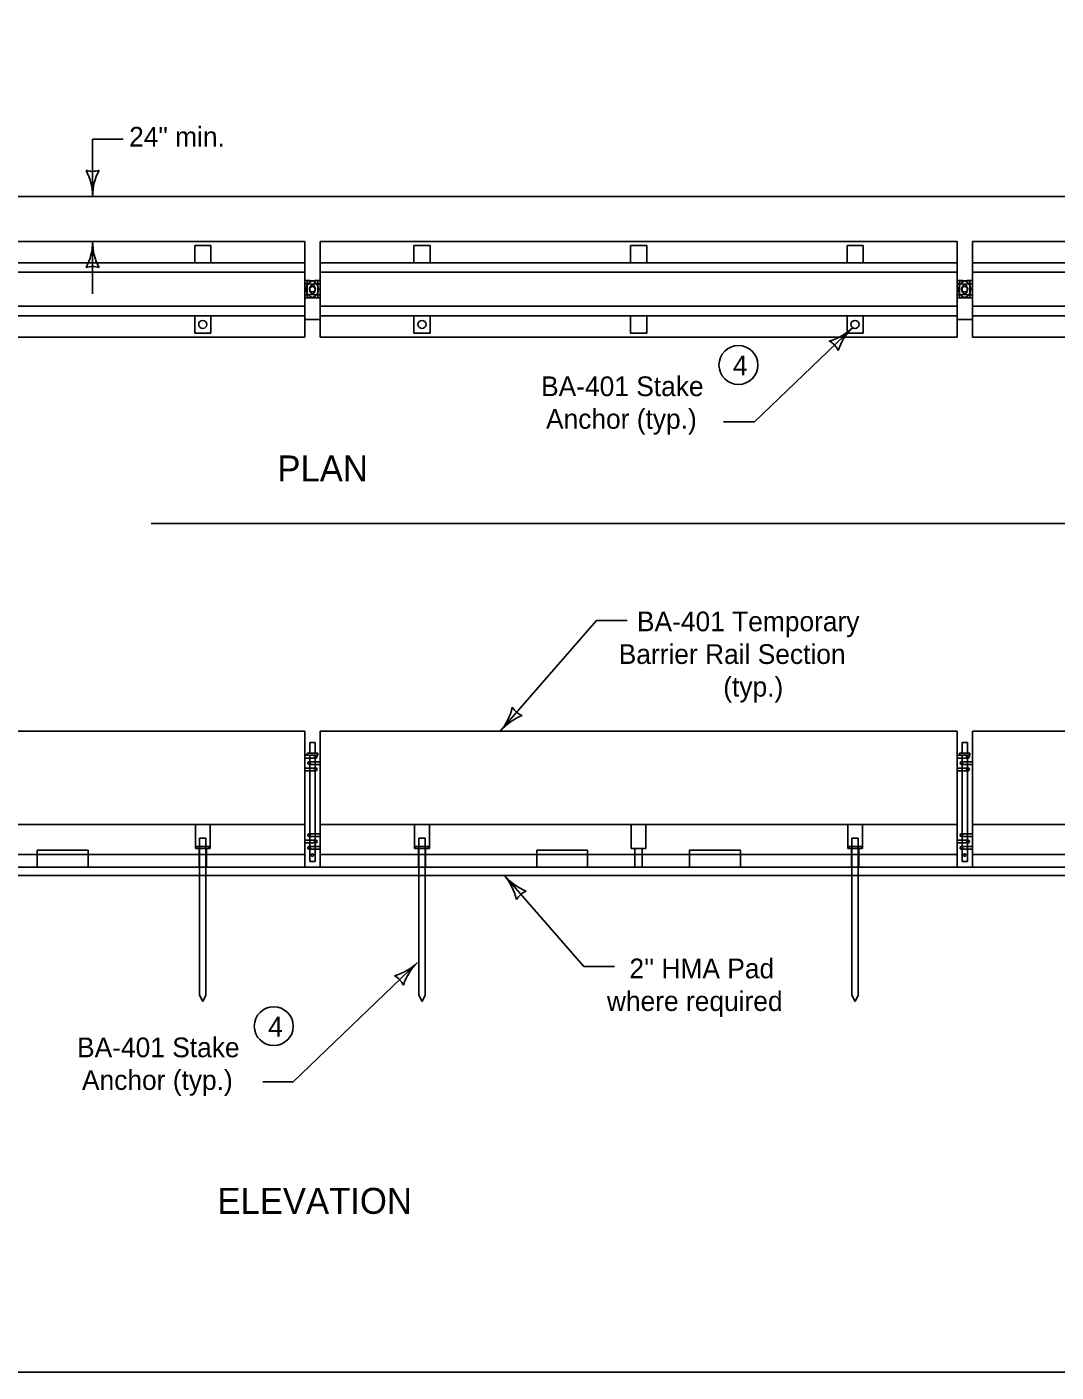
# Model space of a CAD drawing. Extents: x 10028 to 81668, y 3581 to 11018.
# Drawn here: x 18550 to 19344, y 7924 to 8962 of the extents above; entities that cross this region are included whole.
import ezdxf

# ---------------------------------------------------------------- set-up
doc = ezdxf.new("R2010")
doc.units = 0
for name, color, linetype in [('conPaving', 7, 'Continuous'), ('dsnCellsNorthArrow', 7, 'Continuous'), ('dsnTextTabulation', 7, 'Continuous'), ('Level 41', 7, 'Continuous'), ('Level 9', 7, 'Continuous'), ('SheetBorder', 7, 'Continuous')]:
    doc.layers.add(name, color=color, linetype=linetype)

msp = doc.modelspace()

# ---------------------------------------------------------------- linework, layer by layer
at = {"layer": 'conPaving'}
for p, q in [((18683.3, 8313.6), (18682.9, 8313.6)), ((18683.3, 8307.1), (18683.3, 8313.6)), ((18688.6, 8313.6), (18688.2, 8313.6)), ((18688.2, 8313.6), (18688.2, 8307.1)), ((18764.1, 8313.6), (18688.6, 8313.6)), ((18852.5, 8313.6), (18852.1, 8313.6)), ((18852.5, 8307.1), (18852.5, 8313.6)), ((18857.4, 8313.6), (18857.4, 8307.1)), ((19100.7, 8313.6), (19061.3, 8313.6)), ((19186.7, 8307.1), (19186.7, 8313.6)), ((19191.6, 8313.6), (19191.6, 8307.1)), ((18521.1, 8307.1), (18683.3, 8307.1)), ((18688.2, 8307.1), (18852.5, 8307.1)), ((18857.4, 8307.1), (18918.6, 8307.1)), ((18918.6, 8307.1), (19186.7, 8307.1)), ((19191.6, 8307.1), (19355.9, 8307.1))]:
    msp.add_line(p, q, dxfattribs=at)
for points in [[(18682.9, 8313.6), (18597.3, 8313.6), (18557.9, 8313.6), (18521.5, 8313.6), (18521.1, 8313.6)], [(18852.1, 8313.6), (18776.5, 8313.6), (18764.1, 8313.6)], [(19019.2, 8313.6), (18982.7, 8313.6), (18943.4, 8313.6), (18857.7, 8313.6), (18857.4, 8313.6)], [(19061.3, 8313.6), (19024.9, 8313.6), (19019.2, 8313.6)], [(19186.7, 8313.6), (19186.3, 8313.6), (19100.7, 8313.6)], [(19279.9, 8313.6), (19267.5, 8313.6), (19192, 8313.6), (19191.6, 8313.6)], [(19355.9, 8313.6), (19355.5, 8313.6), (19279.9, 8313.6)], [(18918.6, 8307.1), (18918.6, 8307.1)]]:
    msp.add_lwpolyline(points, dxfattribs=at)
msp.add_arc((18950.9, 8334.6), 42.5, 220.4336, 220.435, dxfattribs=at)
at = {"layer": 'dsnTextTabulation'}
for p, q in [((18600.7, 8831), (18600.7, 8875.1)), ((18600.7, 8875.1), (18624.3, 8875.1)), ((18764.4, 8796.1), (18272.9, 8796.1)), ((18600.7, 8755.8), (18600.7, 8796.1)), ((18764.4, 8722.4), (18764.4, 8796.1)), ((19267.8, 8796.1), (18776.3, 8796.1)), ((18776.3, 8722.4), (18776.3, 8796.1)), ((19267.8, 8722.4), (19267.8, 8796.1)), ((19771.2, 8796.1), (19279.7, 8796.1)), ((19279.7, 8722.4), (19279.7, 8796.1)), ((18764.4, 8779.8), (18272.9, 8779.8)), ((19267.8, 8779.8), (18776.3, 8779.8)), ((19771.2, 8779.8), (19279.7, 8779.8)), ((18764.4, 8772.4), (18272.9, 8772.4)), ((19267.8, 8772.4), (18776.3, 8772.4)), ((19771.2, 8772.4), (19279.7, 8772.4)), ((18764.4, 8746.2), (18272.9, 8746.2)), ((18764.4, 8738.8), (18272.9, 8738.8)), ((19267.8, 8746.2), (18776.3, 8746.2)), ((19267.8, 8738.8), (18776.3, 8738.8)), ((19771.2, 8746.2), (19279.7, 8746.2)), ((19771.2, 8738.8), (19279.7, 8738.8)), ((19111.4, 8657), (19187.1, 8729.7)), ((18764.4, 8722.4), (18272.9, 8722.4)), ((19267.8, 8722.4), (18776.3, 8722.4)), ((19771.2, 8722.4), (19279.7, 8722.4)), ((19087.7, 8657), (19111.4, 8657)), ((18645.9, 8578.7), (19777.1, 8578.7)), ((18915.3, 8418.5), (18989.6, 8503.7)), ((18989.6, 8503.7), (19013.2, 8503.7)), ((18272.9, 8418.5), (18764.4, 8418.5)), ((18764.4, 8313.9), (18764.4, 8418.5)), ((18776.3, 8313.9), (18776.3, 8418.5)), ((18776.3, 8418.5), (19267.8, 8418.5)), ((19267.8, 8313.9), (19267.8, 8418.5)), ((19279.7, 8313.9), (19279.7, 8418.5)), ((19279.7, 8418.5), (19771.2, 8418.5)), ((18272.9, 8346.4), (18764.4, 8346.4)), ((18776.3, 8346.4), (19267.8, 8346.4)), ((19279.7, 8346.4), (19771.2, 8346.4)), ((18272.9, 8323.4), (18764.4, 8323.4)), ((18557.9, 8326.7), (18597.3, 8326.7)), ((18557.9, 8313.6), (18557.9, 8323.4)), ((18597.3, 8313.6), (18597.3, 8323.4)), ((18776.3, 8323.4), (19267.8, 8323.4)), ((18943.4, 8326.7), (18982.7, 8326.7)), ((18943.4, 8313.6), (18943.4, 8323.4)), ((18982.7, 8313.6), (18982.7, 8323.4)), ((19061.3, 8326.7), (19100.7, 8326.7)), ((19061.3, 8313.6), (19061.3, 8323.4)), ((19100.7, 8313.6), (19100.7, 8323.4)), ((19279.7, 8323.4), (19771.2, 8323.4)), ((18479.3, 8313.6), (18557.9, 8313.6)), ((18597.3, 8313.6), (18764.1, 8313.6)), ((18776.5, 8313.6), (18943.4, 8313.6)), ((18982.7, 8313.6), (19061.3, 8313.6)), ((19100.7, 8313.6), (19267.5, 8313.6)), ((19279.9, 8313.6), (19446.8, 8313.6)), ((18918.6, 8307.1), (18979.8, 8236.8)), ((18755.6, 8148), (18851.5, 8239.9)), ((18979.8, 8236.8), (19003.4, 8236.8)), ((18732, 8148), (18755.6, 8148))]:
    msp.add_line(p, q, dxfattribs=at)
for centre in [(19099.1, 8700.9), (18740.5, 8190.9)]:
    msp.add_circle(centre, 15, dxfattribs=at)
for centre, radius, start, end in [((18600.7, 8866.7), 16.4, 252.2666, 287.7333), ((18558.2, 8831), 42.5, 360, 28.0725), ((18643.2, 8831), 42.5, 151.9275, 180), ((18558.2, 8796.1), 42.5, 331.9275, 360), ((18643.2, 8796.1), 42.5, 180, 208.0725), ((18600.7, 8760.5), 16.4, 72.2666, 107.7334), ((19157.7, 8760.3), 42.5, 285.7371, 313.8096), ((19216.5, 8699), 42.5, 133.8096, 161.8821), ((19161.4, 8705), 16.4, 26.0762, 61.5429), ((18883, 8446), 42.5, 319.5664, 347.6389), ((18938.5, 8445.6), 16.4, 211.833, 247.2997), ((18947.7, 8390.9), 42.5, 111.4939, 139.5664), ((18886.2, 8279.5), 42.5, 12.3611, 40.4336), ((18950.9, 8334.6), 42.5, 220.4336, 248.5061), ((18941.7, 8279.9), 16.4, 112.7003, 148.167), ((18822.1, 8270.6), 42.5, 285.7371, 313.8096), ((18880.9, 8209.3), 42.5, 133.8096, 161.8821), ((18825.8, 8215.3), 16.4, 26.0762, 61.5429)]:
    msp.add_arc(centre, radius, start, end, dxfattribs=at)
at = {"layer": 'Level 41'}
for p, q in [((18679.5, 8793), (18679.5, 8779.8)), ((18679.5, 8793), (18692, 8793)), ((18692, 8793), (18692, 8779.8)), ((18848.6, 8793), (18861.2, 8793)), ((18848.6, 8793), (18848.6, 8779.8)), ((18861.2, 8793), (18861.2, 8779.8)), ((19015.7, 8793), (19028.3, 8793)), ((19015.7, 8793), (19015.7, 8779.8)), ((19028.3, 8793), (19028.3, 8779.8)), ((19182.9, 8793), (19182.9, 8779.8)), ((19182.9, 8793), (19195.4, 8793)), ((19195.4, 8793), (19195.4, 8779.8)), ((18764.4, 8766), (18768.3, 8766)), ((18764.4, 8763.6), (18768.3, 8763.6)), ((18776.3, 8766), (18772.3, 8766)), ((18776.3, 8763.6), (18772.3, 8763.6)), ((19267.8, 8766), (19271.7, 8766)), ((19267.8, 8763.6), (19271.7, 8763.6)), ((19279.7, 8766), (19275.7, 8766)), ((19279.7, 8763.6), (19275.7, 8763.6)), ((18764.4, 8755), (18768.3, 8755)), ((18764.4, 8752.6), (18768.3, 8752.6)), ((18776.3, 8755), (18772.3, 8755)), ((18776.3, 8752.6), (18772.3, 8752.6)), ((19267.8, 8755), (19271.7, 8755)), ((19267.8, 8752.6), (19271.7, 8752.6)), ((19279.7, 8755), (19275.7, 8755)), ((19279.7, 8752.6), (19275.7, 8752.6)), ((18679.5, 8738.8), (18679.5, 8725.5)), ((18692, 8738.8), (18692, 8725.5)), ((18848.6, 8738.8), (18848.6, 8725.5)), ((18861.2, 8738.8), (18861.2, 8725.5)), ((19015.7, 8738.8), (19015.7, 8725.5)), ((19028.3, 8738.8), (19028.3, 8725.5)), ((19182.9, 8738.8), (19182.9, 8725.5)), ((19195.4, 8738.8), (19195.4, 8725.5)), ((18679.5, 8725.5), (18692, 8725.5)), ((18848.6, 8725.5), (18861.2, 8725.5)), ((19015.7, 8725.5), (19028.3, 8725.5)), ((19182.9, 8725.5), (19195.4, 8725.5)), ((18764.4, 8399.9), (18772.9, 8399.9)), ((18764.4, 8397.7), (18772.9, 8397.7)), ((19267.8, 8399.9), (19276.3, 8399.9)), ((19267.8, 8397.7), (19276.3, 8397.7)), ((18764.4, 8390), (18772.9, 8390)), ((18764.4, 8387.9), (18772.9, 8387.9)), ((18767.8, 8394.9), (18776.3, 8394.9)), ((18767.8, 8392.8), (18776.3, 8392.8)), ((19267.8, 8390), (19276.3, 8390)), ((19267.8, 8387.9), (19276.3, 8387.9)), ((19271.2, 8394.9), (19279.7, 8394.9)), ((19271.2, 8392.8), (19279.7, 8392.8)), ((18680.1, 8327.8), (18680.1, 8346.4)), ((18691.4, 8327.8), (18691.4, 8346.4)), ((18849.2, 8327.8), (18849.2, 8346.4)), ((18860.6, 8327.8), (18860.6, 8346.4)), ((19016.4, 8327.8), (19016.4, 8346.4)), ((19027.7, 8327.8), (19027.7, 8346.4)), ((19183.5, 8327.8), (19183.5, 8346.4)), ((19194.8, 8327.8), (19194.8, 8346.4)), ((18764.4, 8334.3), (18772.9, 8334.3)), ((18767.8, 8339.2), (18776.3, 8339.2)), ((18767.8, 8337.1), (18776.3, 8337.1)), ((19267.8, 8334.3), (19276.3, 8334.3)), ((19271.2, 8339.2), (19279.7, 8339.2)), ((19271.2, 8337.1), (19279.7, 8337.1)), ((18680.1, 8327.8), (18691.4, 8327.8)), ((18682.9, 8313.6), (18682.9, 8327.8)), ((18688.6, 8313.6), (18688.6, 8327.8)), ((18764.4, 8332.2), (18772.9, 8332.2)), ((18767.8, 8329.4), (18776.3, 8329.4)), ((18767.8, 8327.3), (18776.3, 8327.3)), ((18849.2, 8327.8), (18860.6, 8327.8)), ((18852.1, 8313.6), (18852.1, 8327.8)), ((18857.7, 8313.6), (18857.7, 8327.8)), ((19016.4, 8327.8), (19027.7, 8327.8)), ((19019.2, 8313.6), (19019.2, 8327.8)), ((19024.9, 8313.6), (19024.9, 8327.8)), ((19183.5, 8327.8), (19194.8, 8327.8)), ((19186.3, 8313.6), (19186.3, 8327.8)), ((19192, 8313.6), (19192, 8327.8)), ((19267.8, 8332.2), (19276.3, 8332.2)), ((19271.2, 8329.4), (19279.7, 8329.4)), ((19271.2, 8327.3), (19279.7, 8327.3))]:
    msp.add_line(p, q, dxfattribs=at)
for centre, radius in [((18685.7, 8732.2), 3.15), ((18854.9, 8732.2), 3.15), ((19189.1, 8732.2), 3.15), ((18772.9, 8398.8), 1.06), ((19276.3, 8398.8), 1.06), ((18767.8, 8393.9), 1.06), ((18772.9, 8389), 1.06), ((19271.2, 8393.9), 1.06), ((19276.3, 8389), 1.06), ((18767.8, 8338.2), 1.06), ((18772.9, 8333.3), 1.06), ((19271.2, 8338.2), 1.06), ((19276.3, 8333.3), 1.06), ((18767.8, 8328.4), 1.06), ((19271.2, 8328.4), 1.06)]:
    msp.add_circle(centre, radius, dxfattribs=at)
for centre, radius, start, end in [((18772.3, 8759.3), 6.68, 90, 270), ((18772.3, 8759.3), 4.33, 90, 270), ((18768.3, 8759.3), 6.68, 270, 90), ((18768.3, 8759.3), 4.33, 270, 90), ((19275.7, 8759.3), 6.68, 90, 270), ((19275.7, 8759.3), 4.33, 90, 270), ((19271.7, 8759.3), 6.68, 270, 90), ((19271.7, 8759.3), 4.33, 270, 90)]:
    msp.add_arc(centre, radius, start, end, dxfattribs=at)
at = {"layer": 'Level 9'}
for p, q in [((17757.6, 8831), (19777.1, 8831)), ((18776.3, 8796.1), (19267.8, 8796.1)), ((19279.7, 8796.1), (19771.2, 8796.1)), ((18764.4, 8766), (18768.3, 8766)), ((18766.2, 8765.8), (18774.4, 8765.8)), ((18766.2, 8752.7), (18766.2, 8765.8)), ((18769.8, 8765.8), (18770.9, 8765.8)), ((18772.3, 8766), (18776.3, 8766)), ((18774.4, 8765.8), (18774.4, 8752.7)), ((19267.8, 8766), (19271.7, 8766)), ((19269.6, 8765.8), (19277.8, 8765.8)), ((19269.6, 8752.7), (19269.6, 8765.8)), ((19273.2, 8765.8), (19274.3, 8765.8)), ((19275.7, 8766), (19279.7, 8766)), ((19277.8, 8765.8), (19277.8, 8752.7)), ((18768.3, 8752.6), (18764.4, 8752.6)), ((18774.4, 8752.7), (18766.2, 8752.7)), ((18771.1, 8752.7), (18769.5, 8752.7)), ((18776.3, 8752.6), (18772.3, 8752.6)), ((19271.7, 8752.6), (19267.8, 8752.6)), ((19277.8, 8752.7), (19269.6, 8752.7)), ((19274.5, 8752.7), (19272.9, 8752.7)), ((19279.7, 8752.6), (19275.7, 8752.6)), ((18764.4, 8736), (18776.3, 8736)), ((18764.4, 8736), (18776.3, 8736)), ((19267.8, 8736), (19279.7, 8736)), ((19267.8, 8736), (19279.7, 8736)), ((18768.3, 8409.7), (18772.4, 8409.7)), ((18768.3, 8401.5), (18768.3, 8409.7)), ((18772.4, 8409.7), (18772.4, 8401.5)), ((19271.7, 8409.7), (19275.8, 8409.7)), ((19271.7, 8401.5), (19271.7, 8409.7)), ((19275.8, 8409.7), (19275.8, 8401.5)), ((18766.2, 8401.5), (18774.4, 8401.5)), ((18766.2, 8399.9), (18766.2, 8401.5)), ((18774.4, 8399.9), (18766.2, 8399.9)), ((18768.3, 8317.9), (18768.3, 8399.9)), ((18772.4, 8399.9), (18772.4, 8317.9)), ((18774.4, 8401.5), (18774.4, 8399.9)), ((19269.6, 8401.5), (19277.8, 8401.5)), ((19269.6, 8399.9), (19269.6, 8401.5)), ((19277.8, 8399.9), (19269.6, 8399.9)), ((19271.7, 8317.9), (19271.7, 8399.9)), ((19275.8, 8399.9), (19275.8, 8317.9)), ((19277.8, 8401.5), (19277.8, 8399.9)), ((18688.2, 8336), (18683.3, 8336)), ((18683.3, 8336), (18683.3, 8329.4)), ((18688.2, 8336), (18683.3, 8336)), ((18683.3, 8214.8), (18683.3, 8336)), ((18688.2, 8329.4), (18688.2, 8336)), ((18688.2, 8214.8), (18688.2, 8336)), ((18857.4, 8336), (18852.5, 8336)), ((18852.5, 8336), (18852.5, 8329.4)), ((18857.4, 8336), (18852.5, 8336)), ((18852.5, 8214.8), (18852.5, 8336)), ((18857.4, 8329.4), (18857.4, 8336)), ((18857.4, 8214.8), (18857.4, 8336)), ((19191.6, 8336), (19186.7, 8336)), ((19186.7, 8336), (19186.7, 8329.4)), ((19191.6, 8336), (19186.7, 8336)), ((19186.7, 8214.8), (19186.7, 8336)), ((19191.6, 8329.4), (19191.6, 8336)), ((19191.6, 8214.8), (19191.6, 8336)), ((18557.9, 8323.4), (18557.9, 8326.7)), ((18557.9, 8323.4), (18597.3, 8323.4)), ((18597.3, 8323.4), (18597.3, 8326.7)), ((18680.8, 8329.4), (18680.8, 8327.8)), ((18683.3, 8329.4), (18680.8, 8329.4)), ((18680.8, 8327.8), (18680.8, 8329.4)), ((18680.8, 8327.8), (18682.9, 8327.8)), ((18682.9, 8327.8), (18683.3, 8327.8)), ((18688.2, 8329.4), (18683.3, 8329.4)), ((18683.3, 8329.4), (18683.3, 8327.8)), ((18683.3, 8327.8), (18683.3, 8329.4)), ((18683.3, 8329.4), (18688.2, 8329.4)), ((18688.2, 8327.8), (18683.3, 8327.8)), ((18683.3, 8327.8), (18683.3, 8323.4)), ((18683.3, 8327.8), (18688.2, 8327.8)), ((18688.2, 8323.4), (18683.3, 8323.4)), ((18683.3, 8323.4), (18683.3, 8313.6)), ((18683.3, 8323.4), (18688.2, 8323.4)), ((18688.2, 8327.8), (18688.2, 8329.4)), ((18688.2, 8329.4), (18688.2, 8327.8)), ((18688.2, 8323.4), (18688.2, 8327.8)), ((18688.2, 8313.6), (18688.2, 8323.4)), ((18850, 8329.4), (18850, 8327.8)), ((18852.5, 8329.4), (18850, 8329.4)), ((18850, 8327.8), (18850, 8329.4)), ((18850, 8327.8), (18852.1, 8327.8)), ((18852.1, 8327.8), (18852.5, 8327.8)), ((18857.4, 8329.4), (18852.5, 8329.4)), ((18852.5, 8329.4), (18852.5, 8327.8)), ((18852.5, 8327.8), (18852.5, 8329.4)), ((18852.5, 8329.4), (18857.4, 8329.4)), ((18857.4, 8327.8), (18852.5, 8327.8)), ((18852.5, 8327.8), (18852.5, 8323.4)), ((18852.5, 8327.8), (18857.4, 8327.8)), ((18857.4, 8323.4), (18852.5, 8323.4)), ((18852.5, 8323.4), (18852.5, 8313.6)), ((18852.5, 8323.4), (18857.4, 8323.4)), ((18857.4, 8327.8), (18857.4, 8329.4)), ((18857.4, 8329.4), (18857.4, 8327.8)), ((18857.4, 8323.4), (18857.4, 8327.8)), ((18857.4, 8313.6), (18857.4, 8323.4)), ((18943.4, 8323.4), (18943.4, 8326.7)), ((18943.4, 8323.4), (18982.7, 8323.4)), ((18982.7, 8323.4), (18982.7, 8326.7)), ((19061.3, 8323.4), (19061.3, 8326.7)), ((19061.3, 8323.4), (19100.7, 8323.4)), ((19100.7, 8323.4), (19100.7, 8326.7)), ((19184.2, 8329.4), (19184.2, 8327.8)), ((19186.7, 8329.4), (19184.2, 8329.4)), ((19184.2, 8327.8), (19184.2, 8329.4)), ((19184.2, 8327.8), (19186.3, 8327.8)), ((19186.3, 8327.8), (19186.7, 8327.8)), ((19191.6, 8329.4), (19186.7, 8329.4)), ((19186.7, 8329.4), (19186.7, 8327.8)), ((19186.7, 8327.8), (19186.7, 8329.4)), ((19186.7, 8329.4), (19191.6, 8329.4)), ((19191.6, 8327.8), (19186.7, 8327.8)), ((19186.7, 8327.8), (19186.7, 8323.4)), ((19186.7, 8327.8), (19191.6, 8327.8)), ((19191.6, 8323.4), (19186.7, 8323.4)), ((19186.7, 8323.4), (19186.7, 8313.6)), ((19186.7, 8323.4), (19191.6, 8323.4)), ((19191.6, 8327.8), (19191.6, 8329.4)), ((19191.6, 8329.4), (19191.6, 8327.8)), ((19191.6, 8323.4), (19191.6, 8327.8)), ((19191.6, 8313.6), (19191.6, 8323.4)), ((17462, 8313.6), (20253.1, 8313.6)), ((18688.2, 8313.6), (18683.3, 8313.6)), ((18683.3, 8313.6), (18683.3, 8307.1)), ((18683.3, 8313.6), (18688.2, 8313.6)), ((18688.2, 8307.1), (18688.2, 8313.6)), ((18764.1, 8313.6), (18764.4, 8313.9)), ((18772.4, 8317.9), (18768.3, 8317.9)), ((18776.3, 8313.9), (18776.5, 8313.6)), ((18857.4, 8313.6), (18852.5, 8313.6)), ((18852.5, 8313.6), (18852.5, 8307.1)), ((18852.5, 8313.6), (18857.4, 8313.6)), ((18857.4, 8307.1), (18857.4, 8313.6)), ((19191.6, 8313.6), (19186.7, 8313.6)), ((19186.7, 8313.6), (19186.7, 8307.1)), ((19186.7, 8313.6), (19191.6, 8313.6)), ((19191.6, 8307.1), (19191.6, 8313.6)), ((19267.5, 8313.6), (19267.8, 8313.9)), ((19275.8, 8317.9), (19271.7, 8317.9)), ((19279.7, 8313.9), (19279.9, 8313.6)), ((17757.6, 8307.1), (19777.1, 8307.1)), ((18688.2, 8307.1), (18683.3, 8307.1)), ((18683.3, 8307.1), (18683.3, 8214.8)), ((18683.3, 8307.1), (18688.2, 8307.1)), ((18688.2, 8214.8), (18688.2, 8307.1)), ((18857.4, 8307.1), (18852.5, 8307.1)), ((18852.5, 8307.1), (18852.5, 8214.8)), ((18852.5, 8307.1), (18857.4, 8307.1)), ((18857.4, 8214.8), (18857.4, 8307.1)), ((19191.6, 8307.1), (19186.7, 8307.1)), ((19186.7, 8307.1), (19186.7, 8214.8)), ((19186.7, 8307.1), (19191.6, 8307.1)), ((19191.6, 8214.8), (19191.6, 8307.1)), ((18683.3, 8214.8), (18685.7, 8209.8)), ((18683.3, 8214.8), (18685.7, 8209.8)), ((18685.7, 8209.8), (18688.2, 8214.8)), ((18685.7, 8209.8), (18688.2, 8214.8)), ((18852.5, 8214.8), (18854.9, 8209.8)), ((18852.5, 8214.8), (18854.9, 8209.8)), ((18854.9, 8209.8), (18857.4, 8214.8)), ((18854.9, 8209.8), (18857.4, 8214.8)), ((19186.7, 8214.8), (19189.1, 8209.8)), ((19186.7, 8214.8), (19189.1, 8209.8)), ((19189.1, 8209.8), (19191.6, 8214.8)), ((19189.1, 8209.8), (19191.6, 8214.8))]:
    msp.add_line(p, q, dxfattribs=at)
for points in [[(19777.1, 8831), (18443, 8831), (18258, 8831), (18258, 8831)], [(18272.9, 8796.1), (18443, 8796.1), (18764.4, 8796.1)], [(18764.4, 8796.1), (18764.4, 8779.8), (18764.4, 8772.4), (18764.4, 8766)], [(18776.3, 8766), (18776.3, 8772.4), (18776.3, 8779.8), (18776.3, 8796.1)], [(19267.8, 8796.1), (19267.8, 8779.8), (19267.8, 8772.4), (19267.8, 8766)], [(19279.7, 8766), (19279.7, 8772.4), (19279.7, 8779.8), (19279.7, 8796.1)], [(18764.4, 8752.6), (18764.4, 8746.2), (18764.4, 8738.8), (18764.4, 8736)], [(18776.3, 8736), (18776.3, 8738.8), (18776.3, 8746.2), (18776.3, 8752.6)], [(19267.8, 8752.6), (19267.8, 8746.2), (19267.8, 8738.8), (19267.8, 8736)], [(19279.7, 8736), (19279.7, 8738.8), (19279.7, 8746.2), (19279.7, 8752.6)], [(18680.8, 8329.4), (18690.7, 8329.4), (18690.7, 8327.8), (18680.8, 8327.8)], [(18690.7, 8327.8), (18690.7, 8329.4), (18688.2, 8329.4)], [(18688.2, 8327.8), (18688.6, 8327.8), (18690.7, 8327.8)], [(18850, 8329.4), (18859.8, 8329.4), (18859.8, 8327.8), (18850, 8327.8)], [(18859.8, 8327.8), (18859.8, 8329.4), (18857.4, 8329.4)], [(18857.4, 8327.8), (18857.7, 8327.8), (18859.8, 8327.8)], [(19184.2, 8329.4), (19194.1, 8329.4), (19194.1, 8327.8), (19184.2, 8327.8)], [(19194.1, 8327.8), (19194.1, 8329.4), (19191.6, 8329.4)], [(19191.6, 8327.8), (19192, 8327.8), (19194.1, 8327.8)]]:
    msp.add_lwpolyline(points, dxfattribs=at)
for centre, radius in [((18770.3, 8759.3), 2.05), ((19273.7, 8759.3), 2.05), ((18770.3, 8322.9), 1.02), ((19273.7, 8322.9), 1.02)]:
    msp.add_circle(centre, radius, dxfattribs=at)
for centre, start, end in [((18768.3, 8759.3), 77.6043, 90), ((18772.3, 8759.3), 90, 102.3957), ((19271.7, 8759.3), 77.6043, 90), ((19275.7, 8759.3), 90, 102.3957), ((18768.3, 8759.3), 270, 280.2309), ((18772.3, 8759.3), 259.7691, 270), ((19271.7, 8759.3), 270, 280.2309), ((19275.7, 8759.3), 259.7691, 270)]:
    msp.add_arc(centre, 6.68, start, end, dxfattribs=at)
at = {"layer": 'SheetBorder'}
msp.add_lwpolyline([(17332.5, 9944), (20467.5, 9944), (20467.5, 7924), (17332.5, 7924)], close=True, dxfattribs=at)

# ---------------------------------------------------------------- texts
at = {"layer": 'dsnCellsNorthArrow'}
for s, height, p in [('24" min.', 15.2, (18628.9, 8869.4)), ('BA-401 Stake', 15.2, (18946.8, 8676.9)), ('Anchor (typ.)', 15.2, (18950.6, 8651.7)), ('PLAN', 20, (18743.3, 8611.1)), ('BA-401 Temporary', 15.2, (19020.8, 8495.5)), ('Barrier Rail Section', 15.2, (19006.7, 8470.3)), ('(typ.)', 15.2, (19087.4, 8445.1)), ("2'' HMA Pad", 15.2, (19015, 8227.8)), ('where required', 15.2, (18997.6, 8202.6)), ('BA-401 Stake', 15.2, (18588.7, 8166.9)), ('Anchor (typ.)', 15.2, (18592.5, 8141.7)), ('ELEVATION', 20, (18697, 8046.1))]:
    msp.add_text(s, height=height, dxfattribs=at).set_placement(p)
at = {"layer": 'dsnTextTabulation'}
for p in [(19094.8, 8693), (18736.2, 8182.9)]:
    msp.add_text('4', height=15.2, dxfattribs=at).set_placement(p)

doc.saveas('drawing.dxf')
